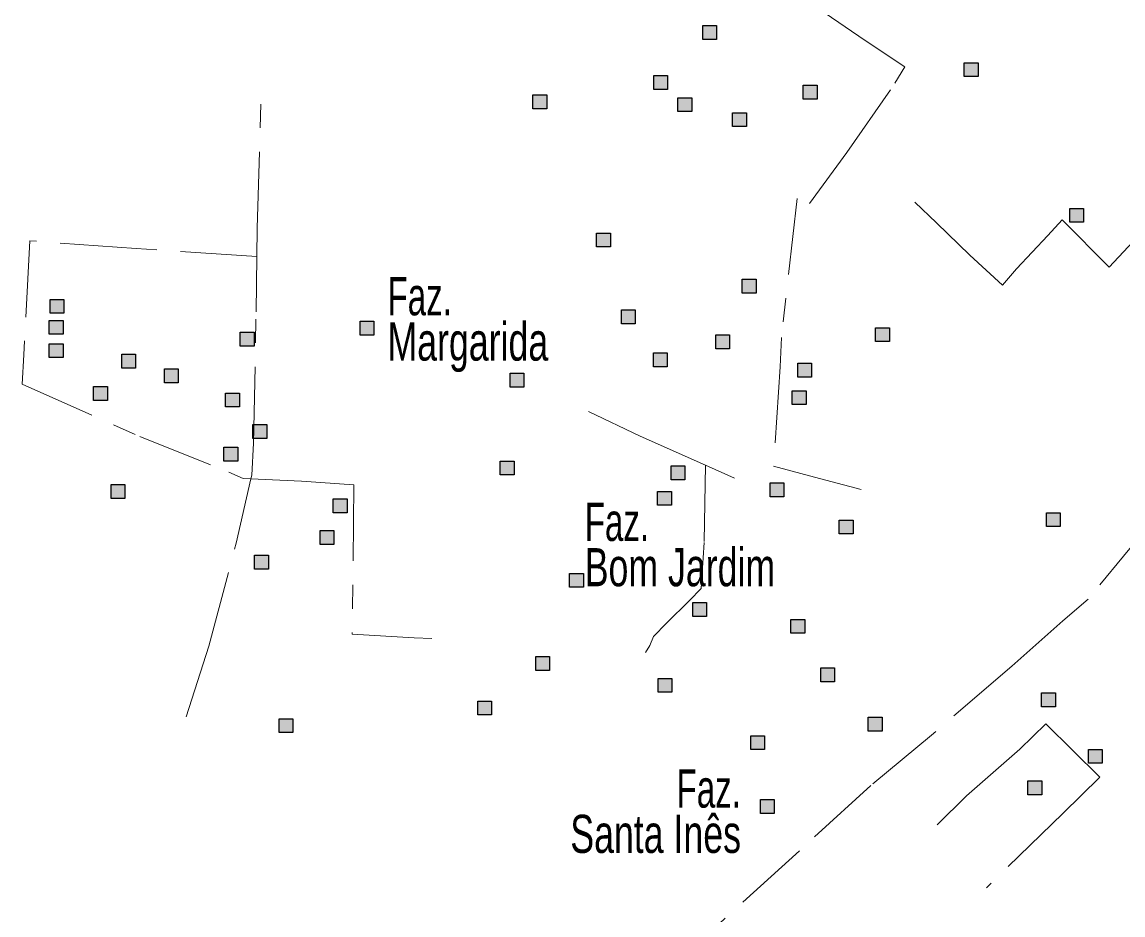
# Model space of a CAD drawing. Extents: x 445.6 to 500, y 8618.1 to 8673.4.
# Drawn here: x 479.394 to 484.012, y 8644.258 to 8648.002 of the extents above; entities that cross this region are included whole.
import ezdxf
from ezdxf.enums import TextEntityAlignment as Align

# ---------------------------------------------------------------- set-up
doc = ezdxf.new("R2010")
doc.units = 0
doc.header["$LTSCALE"] = 0.064
doc.linetypes.add('DOT_DASHED', pattern=[7.7, 5, -1.2, 0.3, -1.2])
doc.layers.add('2', color=7, linetype='Continuous', lineweight=25)
doc.layers.add('22', color=7, linetype='DOT_DASHED', lineweight=13)
doc.layers.add('61', color=7, linetype='Continuous')

msp = doc.modelspace()

# ---------------------------------------------------------------- hatches: boundary and pattern name
at = {"layer": '2'}
for points in [[(482.2496, 8647.9877), (482.3076, 8647.9877), (482.3076, 8647.9297), (482.2496, 8647.9297)], [(483.3464, 8647.8319), (483.4044, 8647.8319), (483.4044, 8647.7739), (483.3464, 8647.7739)], [(482.0436, 8647.7778), (482.1016, 8647.7778), (482.1016, 8647.7198), (482.0436, 8647.7198)], [(482.6708, 8647.737), (482.7288, 8647.737), (482.7288, 8647.679), (482.6708, 8647.679)], [(481.5369, 8647.6965), (481.5949, 8647.6965), (481.5949, 8647.6385), (481.5369, 8647.6385)], [(482.1456, 8647.6852), (482.2036, 8647.6852), (482.2036, 8647.6272), (482.1456, 8647.6272)], [(482.3746, 8647.622), (482.4326, 8647.622), (482.4326, 8647.564), (482.3746, 8647.564)], [(483.7891, 8647.2205), (483.8471, 8647.2205), (483.8471, 8647.1625), (483.7891, 8647.1625)], [(481.8038, 8647.1172), (481.8618, 8647.1172), (481.8618, 8647.0592), (481.8038, 8647.0592)], [(482.4151, 8646.9241), (482.4731, 8646.9241), (482.4731, 8646.8661), (482.4151, 8646.8661)], [(479.5115, 8646.8393), (479.5695, 8646.8393), (479.5695, 8646.7813), (479.5115, 8646.7813)], [(481.9085, 8646.7953), (481.9665, 8646.7953), (481.9665, 8646.7373), (481.9085, 8646.7373)], [(479.5081, 8646.7513), (479.5661, 8646.7513), (479.5661, 8646.6933), (479.5081, 8646.6933)], [(480.812, 8646.7479), (480.87, 8646.7479), (480.87, 8646.6899), (480.812, 8646.6899)], [(482.9748, 8646.7206), (483.0328, 8646.7206), (483.0328, 8646.6626), (482.9748, 8646.6626)], [(480.3095, 8646.7016), (480.3675, 8646.7016), (480.3675, 8646.6436), (480.3095, 8646.6436)], [(482.3037, 8646.6903), (482.3617, 8646.6903), (482.3617, 8646.6323), (482.3037, 8646.6323)], [(479.5081, 8646.653), (479.5661, 8646.653), (479.5661, 8646.595), (479.5081, 8646.595)], [(482.0427, 8646.6146), (482.1007, 8646.6146), (482.1007, 8646.5566), (482.0427, 8646.5566)], [(479.8121, 8646.609), (479.8701, 8646.609), (479.8701, 8646.551), (479.8121, 8646.551)], [(482.6482, 8646.5717), (482.7062, 8646.5717), (482.7062, 8646.5137), (482.6482, 8646.5137)], [(479.9912, 8646.548), (480.0492, 8646.548), (480.0492, 8646.49), (479.9912, 8646.49)], [(481.4414, 8646.5299), (481.4994, 8646.5299), (481.4994, 8646.4719), (481.4414, 8646.4719)], [(479.6939, 8646.4734), (479.7519, 8646.4734), (479.7519, 8646.4154), (479.6939, 8646.4154)], [(480.2479, 8646.4463), (480.3059, 8646.4463), (480.3059, 8646.3883), (480.2479, 8646.3883)], [(482.6246, 8646.4565), (482.6826, 8646.4565), (482.6826, 8646.3985), (482.6246, 8646.3985)], [(480.3627, 8646.3142), (480.4207, 8646.3142), (480.4207, 8646.2562), (480.3627, 8646.2562)], [(480.2411, 8646.2193), (480.2991, 8646.2193), (480.2991, 8646.1613), (480.2411, 8646.1613)], [(481.4002, 8646.1611), (481.4582, 8646.1611), (481.4582, 8646.1031), (481.4002, 8646.1031)], [(482.1163, 8646.1408), (482.1743, 8646.1408), (482.1743, 8646.0828), (482.1163, 8646.0828)], [(479.7678, 8646.063), (479.8258, 8646.063), (479.8258, 8646.005), (479.7678, 8646.005)], [(482.5318, 8646.0696), (482.5898, 8646.0696), (482.5898, 8646.0116), (482.5318, 8646.0116)], [(482.0602, 8646.034), (482.1182, 8646.034), (482.1182, 8645.976), (482.0602, 8645.976)], [(480.6992, 8646.0025), (480.7572, 8646.0025), (480.7572, 8645.9445), (480.6992, 8645.9445)], [(483.6914, 8645.9447), (483.7494, 8645.9447), (483.7494, 8645.8867), (483.6914, 8645.8867)], [(482.8222, 8645.9138), (482.8802, 8645.9138), (482.8802, 8645.8558), (482.8222, 8645.8558)], [(480.6443, 8645.8699), (480.7023, 8645.8699), (480.7023, 8645.8119), (480.6443, 8645.8119)], [(480.3694, 8645.7661), (480.4274, 8645.7661), (480.4274, 8645.7081), (480.3694, 8645.7081)], [(481.6907, 8645.6902), (481.7487, 8645.6902), (481.7487, 8645.6322), (481.6907, 8645.6322)], [(482.2075, 8645.5682), (482.2655, 8645.5682), (482.2655, 8645.5102), (482.2075, 8645.5102)], [(482.6196, 8645.497), (482.6776, 8645.497), (482.6776, 8645.439), (482.6196, 8645.439)], [(481.5488, 8645.3412), (481.6068, 8645.3412), (481.6068, 8645.2832), (481.5488, 8645.2832)], [(482.7446, 8645.2938), (482.8026, 8645.2938), (482.8026, 8645.2358), (482.7446, 8645.2358)], [(482.0622, 8645.2497), (482.1202, 8645.2497), (482.1202, 8645.1917), (482.0622, 8645.1917)], [(483.6711, 8645.1892), (483.7291, 8645.1892), (483.7291, 8645.1312), (483.6711, 8645.1312)], [(481.3056, 8645.1549), (481.3636, 8645.1549), (481.3636, 8645.0969), (481.3056, 8645.0969)], [(480.472, 8645.0805), (480.53, 8645.0805), (480.53, 8645.0225), (480.472, 8645.0225)], [(482.9439, 8645.0871), (483.0019, 8645.0871), (483.0019, 8645.0291), (482.9439, 8645.0291)], [(482.4507, 8645.0092), (482.5087, 8645.0092), (482.5087, 8644.9512), (482.4507, 8644.9512)], [(483.867, 8644.9521), (483.925, 8644.9521), (483.925, 8644.8941), (483.867, 8644.8941)], [(483.6137, 8644.8199), (483.6717, 8644.8199), (483.6717, 8644.7619), (483.6137, 8644.7619)], [(482.4912, 8644.7415), (482.5492, 8644.7415), (482.5492, 8644.6835), (482.4912, 8644.6835)]]:
    msp.add_hatch(color=256, dxfattribs=at).paths.add_polyline_path(points)

# ---------------------------------------------------------------- linework, layer by layer
for points in [[(482.2496, 8647.9877), (482.3076, 8647.9877), (482.3076, 8647.9297), (482.2496, 8647.9297)], [(483.3464, 8647.8319), (483.4044, 8647.8319), (483.4044, 8647.7739), (483.3464, 8647.7739)], [(482.0436, 8647.7778), (482.1016, 8647.7778), (482.1016, 8647.7198), (482.0436, 8647.7198)], [(482.6708, 8647.737), (482.7288, 8647.737), (482.7288, 8647.679), (482.6708, 8647.679)], [(481.5369, 8647.6965), (481.5949, 8647.6965), (481.5949, 8647.6385), (481.5369, 8647.6385)], [(482.1456, 8647.6852), (482.2036, 8647.6852), (482.2036, 8647.6272), (482.1456, 8647.6272)], [(482.3746, 8647.622), (482.4326, 8647.622), (482.4326, 8647.564), (482.3746, 8647.564)], [(483.7891, 8647.2205), (483.8471, 8647.2205), (483.8471, 8647.1625), (483.7891, 8647.1625)], [(481.8038, 8647.1172), (481.8618, 8647.1172), (481.8618, 8647.0592), (481.8038, 8647.0592)], [(482.4151, 8646.9241), (482.4731, 8646.9241), (482.4731, 8646.8661), (482.4151, 8646.8661)], [(479.5115, 8646.8393), (479.5695, 8646.8393), (479.5695, 8646.7813), (479.5115, 8646.7813)], [(481.9085, 8646.7953), (481.9665, 8646.7953), (481.9665, 8646.7373), (481.9085, 8646.7373)], [(479.5081, 8646.7513), (479.5661, 8646.7513), (479.5661, 8646.6933), (479.5081, 8646.6933)], [(480.812, 8646.7479), (480.87, 8646.7479), (480.87, 8646.6899), (480.812, 8646.6899)], [(482.9748, 8646.7206), (483.0328, 8646.7206), (483.0328, 8646.6626), (482.9748, 8646.6626)], [(480.3095, 8646.7016), (480.3675, 8646.7016), (480.3675, 8646.6436), (480.3095, 8646.6436)], [(482.3037, 8646.6903), (482.3617, 8646.6903), (482.3617, 8646.6323), (482.3037, 8646.6323)], [(479.5081, 8646.653), (479.5661, 8646.653), (479.5661, 8646.595), (479.5081, 8646.595)], [(482.0427, 8646.6146), (482.1007, 8646.6146), (482.1007, 8646.5566), (482.0427, 8646.5566)], [(479.8121, 8646.609), (479.8701, 8646.609), (479.8701, 8646.551), (479.8121, 8646.551)], [(482.6482, 8646.5717), (482.7062, 8646.5717), (482.7062, 8646.5137), (482.6482, 8646.5137)], [(479.9912, 8646.548), (480.0492, 8646.548), (480.0492, 8646.49), (479.9912, 8646.49)], [(481.4414, 8646.5299), (481.4994, 8646.5299), (481.4994, 8646.4719), (481.4414, 8646.4719)], [(479.6939, 8646.4734), (479.7519, 8646.4734), (479.7519, 8646.4154), (479.6939, 8646.4154)], [(480.2479, 8646.4463), (480.3059, 8646.4463), (480.3059, 8646.3883), (480.2479, 8646.3883)], [(482.6246, 8646.4565), (482.6826, 8646.4565), (482.6826, 8646.3985), (482.6246, 8646.3985)], [(480.3627, 8646.3142), (480.4207, 8646.3142), (480.4207, 8646.2562), (480.3627, 8646.2562)], [(480.2411, 8646.2193), (480.2991, 8646.2193), (480.2991, 8646.1613), (480.2411, 8646.1613)], [(481.4002, 8646.1611), (481.4582, 8646.1611), (481.4582, 8646.1031), (481.4002, 8646.1031)], [(482.1163, 8646.1408), (482.1743, 8646.1408), (482.1743, 8646.0828), (482.1163, 8646.0828)], [(479.7678, 8646.063), (479.8258, 8646.063), (479.8258, 8646.005), (479.7678, 8646.005)], [(482.5318, 8646.0696), (482.5898, 8646.0696), (482.5898, 8646.0116), (482.5318, 8646.0116)], [(482.0602, 8646.034), (482.1182, 8646.034), (482.1182, 8645.976), (482.0602, 8645.976)], [(480.6992, 8646.0025), (480.7572, 8646.0025), (480.7572, 8645.9445), (480.6992, 8645.9445)], [(483.6914, 8645.9447), (483.7494, 8645.9447), (483.7494, 8645.8867), (483.6914, 8645.8867)], [(482.8222, 8645.9138), (482.8802, 8645.9138), (482.8802, 8645.8558), (482.8222, 8645.8558)], [(480.6443, 8645.8699), (480.7023, 8645.8699), (480.7023, 8645.8119), (480.6443, 8645.8119)], [(480.3694, 8645.7661), (480.4274, 8645.7661), (480.4274, 8645.7081), (480.3694, 8645.7081)], [(481.6907, 8645.6902), (481.7487, 8645.6902), (481.7487, 8645.6322), (481.6907, 8645.6322)], [(482.2075, 8645.5682), (482.2655, 8645.5682), (482.2655, 8645.5102), (482.2075, 8645.5102)], [(482.6196, 8645.497), (482.6776, 8645.497), (482.6776, 8645.439), (482.6196, 8645.439)], [(481.5488, 8645.3412), (481.6068, 8645.3412), (481.6068, 8645.2832), (481.5488, 8645.2832)], [(482.7446, 8645.2938), (482.8026, 8645.2938), (482.8026, 8645.2358), (482.7446, 8645.2358)], [(482.0622, 8645.2497), (482.1202, 8645.2497), (482.1202, 8645.1917), (482.0622, 8645.1917)], [(483.6711, 8645.1892), (483.7291, 8645.1892), (483.7291, 8645.1312), (483.6711, 8645.1312)], [(481.3056, 8645.1549), (481.3636, 8645.1549), (481.3636, 8645.0969), (481.3056, 8645.0969)], [(480.472, 8645.0805), (480.53, 8645.0805), (480.53, 8645.0225), (480.472, 8645.0225)], [(482.9439, 8645.0871), (483.0019, 8645.0871), (483.0019, 8645.0291), (482.9439, 8645.0291)], [(482.4507, 8645.0092), (482.5087, 8645.0092), (482.5087, 8644.9512), (482.4507, 8644.9512)], [(483.867, 8644.9521), (483.925, 8644.9521), (483.925, 8644.8941), (483.867, 8644.8941)], [(483.6137, 8644.8199), (483.6717, 8644.8199), (483.6717, 8644.7619), (483.6137, 8644.7619)], [(482.4912, 8644.7415), (482.5492, 8644.7415), (482.5492, 8644.6835), (482.4912, 8644.6835)]]:
    msp.add_lwpolyline(points, close=True, dxfattribs=at)
at = {"layer": '22'}
for points in [[(482.6971, 8647.2415), (482.8535, 8647.456), (483.0554, 8647.746), (483.0969, 8647.8151), (482.931, 8647.9255), (482.6793, 8648.0986), (482.5479, 8648.1901)], [(483.139, 8647.2469), (483.2301, 8647.1603), (483.3695, 8647.0248), (483.507, 8646.8983), (483.5649, 8646.967), (483.697, 8647.1079), (483.7568, 8647.173), (483.954, 8646.9742), (484.1151, 8647.1477), (484.2301, 8647.2407), (484.4201, 8647.4467), (484.5486, 8647.5696), (484.6753, 8647.7088), (484.7555, 8647.7893), (484.7932, 8647.8269)], [(480.3784, 8647.0191), (480.3797, 8647.1386), (480.3979, 8647.7183)], [(482.6454, 8647.2619), (482.5799, 8646.6793), (482.5747, 8646.557), (482.5466, 8646.1397), (482.7176, 8646.0938), (482.9133, 8646.0427)], [(480.3784, 8647.0191), (479.8733, 8647.0521), (479.4267, 8647.085), (479.4011, 8646.6062), (479.3939, 8646.4835), (479.888, 8646.2642), (480.2614, 8646.1143), (480.3211, 8646.0878), (480.3541, 8646.0863)], [(480.3541, 8646.0863), (480.3576, 8646.1016), (480.3649, 8646.2369), (480.376, 8646.7877), (480.3784, 8647.0191)], [(481.7704, 8646.3686), (481.987, 8646.2661), (482.2614, 8646.1441), (482.3826, 8646.0902)], [(482.2614, 8646.1441), (482.255, 8645.82), (482.2422, 8645.6263), (482.1937, 8645.5766), (482.0967, 8645.4823), (482.0431, 8645.4262), (482.0278, 8645.3879), (482.0095, 8645.3585)], [(480.0828, 8645.0889), (480.1782, 8645.3852), (480.2917, 8645.8165), (480.3541, 8646.0863)], [(480.3541, 8646.0863), (480.5664, 8646.0769), (480.786, 8646.0623), (480.7792, 8645.4353), (481.0391, 8645.4207), (481.1135, 8645.4171)], [(484.1191, 8645.8895), (483.8667, 8645.5828), (483.7598, 8645.4913), (483.5461, 8645.3008), (483.2095, 8645.0121), (482.955, 8644.8012), (482.6548, 8644.5268), (482.2926, 8644.1975), (482.0016, 8643.9391), (481.8718, 8643.8273), (481.6555, 8643.6266), (481.4015, 8643.4048)], [(483.2331, 8644.6357), (483.3552, 8644.7577), (483.5791, 8644.9533), (483.6885, 8645.06), (483.915, 8644.8364), (483.7598, 8644.684), (483.4392, 8644.3715)]]:
    msp.add_lwpolyline(points, dxfattribs=at)

# ---------------------------------------------------------------- texts
at = {"layer": '61'}
for s, width, p in [('Faz.', 0.65, (480.9269, 8646.7726)), ('Margarida', 0.7, (480.9269, 8646.5826)), ('Faz.', 0.65, (481.7543, 8645.8264)), ('Bom Jardim', 0.7, (481.7543, 8645.6364))]:
    msp.add_text(s, height=0.16, dxfattribs=dict(at, width=width)).set_placement(p)
for s, width, p in [('Faz.', 0.65, (482.4099, 8644.7081)), ('Santa Inês', 0.7, (482.4099, 8644.5181))]:
    msp.add_text(s, height=0.16, dxfattribs=dict(at, width=width)).set_placement(p, align=Align.RIGHT)

doc.saveas('drawing.dxf')
